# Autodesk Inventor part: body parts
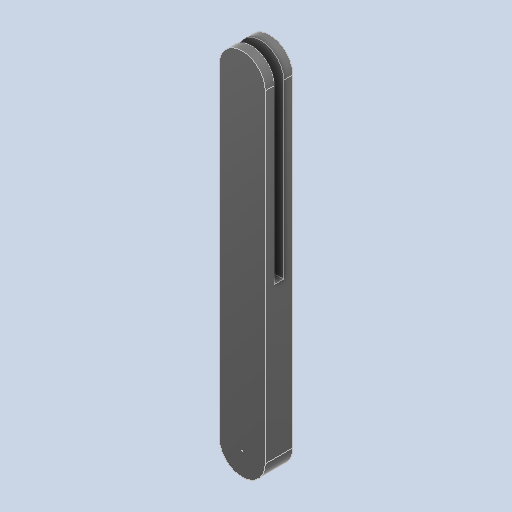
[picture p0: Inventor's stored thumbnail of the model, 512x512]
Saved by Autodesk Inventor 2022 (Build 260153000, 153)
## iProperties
Created: 2022-02
Part Number: body parts
Material: PVC-Piping
Document SubType Name: Modeling
Designer: joshw
Density: 1.4 g/cm^3
Appearance: Smooth - Black
Author: joshw
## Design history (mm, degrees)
sketch "Sketch1"
  geometry: L1 (21.059, 9.49)-(21.059, 9.49); L2 (21.694, 8.855)-(21.694, -0.035); L3 (21.059, -0.67)-(21.059, -0.67); L4 (20.424, -0.035)-(20.424, 8.855); A1 r 0.635 centre (21.059, 8.855) between (21.059, 9.49) and (20.424, 8.855); A2 r 0.635 centre (21.059, 8.855) between (21.694, 8.855) and (21.059, 9.49); A3 r 0.635 centre (21.059, -0.035) between (21.059, -0.67) and (21.694, -0.035); A4 r 0.635 centre (21.059, -0.035) between (20.424, -0.035) and (21.059, -0.67); 6 further points
  constraints: 8 end point, 8 point on circle, 8 tangent, 6 point on line, 4 centre point, 3 equal radius, 2 parallel, 1 horizontal, 1 perpendicular
  dimensions: "d0" = 1.27 distance of point (21.694, -0.67) point (20.424, -0.67); "d1" = 10.16 distance of point (21.694, 9.49) point (21.694, -0.67); "d2" = 0.635 radius of A1
extrude "Extrusion1" new body sketch "Sketch1" stored distance "d3" = 0.762; taper "d4" = 0 deg
sketch "Sketch2"
  geometry: L1 (20.424, 8.855)-(20.424, -0.035) reference; L2 (21.694, -0.035)-(21.694, 8.855) reference; L3 (20.424, 4.112)-(21.694, 4.112); L4 (21.694, 8.855)-(21.694, -0.035) reference; C1 r 0.064 at (21.059, 8.855); A1 r 0.635 centre (21.059, 8.855) between (21.694, 8.855) and (20.424, 8.855) reference; A2 r 0.635 centre (21.059, 8.855) between (21.694, 8.855) and (20.424, 8.855); 4 further points
  constraints: 3 end point, 3 point on line, 2 centre point, 2 coincident, 2 point on circle, 1 perpendicular
  dimensions: "d5" = 0.127 diameter of C1
extrude "Extrusion2" cut sketch "Sketch2" stored distance "d6" = 0.254; taper "d7" = 0 deg
workplane "Work Plane1"
sketch "Sketch4"
  geometry: C1 r 0.013 at (21.059, -0.035); A1 r 0.635 centre (21.059, -0.035) between (20.424, -0.035) and (21.694, -0.035) reference; 1 further point
  constraints: 1 centre point, 1 coincident
  dimensions: "d11" = 0.0254 diameter of C1
extrude "Extrusion4" cut sketch "Sketch4" stored distance "d12" = 1.8415; taper "d13" = 0 deg
body "Solid1"
